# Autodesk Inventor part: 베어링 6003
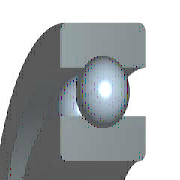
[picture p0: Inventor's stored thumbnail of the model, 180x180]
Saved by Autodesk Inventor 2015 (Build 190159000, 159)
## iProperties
Created: 2012-02
Part Number: 베어링 6003
Material: 강철, 연강
Description: 깊은 그루브 볼 베어링
Document SubType Name: Modeling
Standard: KS B 2023
Designer: mduedu
Standards Organization: KS
Language: ko-KR
Size Designation: 6003 - 17 x 35 x 10
Categories: <MemberInstance><Categories><Category DisplayName="샤프트 부품" InternalName="7f7aeb1f-a693-4053-b835-cee3144e0d98" Mnemonic="SHFT"><Category DisplayName="베어링" Inter
Density: 7.86 g/cm^3
Appearance: Steel
Mass: 39.0276 g
Surface Area: 48.7538 cm^2
Volume: 4.96535 cm^3
IsCustomPart: 1
Author: mduedu
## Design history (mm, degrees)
sketch "스케치" dims "d0" = 4.68 (= -0.26 x WD + 0.26 x BD)
  geometry: L1 (2.66, 13)-(7.34, 13); L2 (5, 13)-(5, 10.66); L3 (5, 13)-(5, 15.34); L4 (3.261, 11.434)-(0, 11.434); L5 (0, 8.5)-(10, 8.5); L6 (3.261, 14.566)-(0, 14.566); L7 (0, 17.5)-(10, 17.5); L8 (10, 8.5)-(10, 11.434); L9 (6.739, 11.434)-(10, 11.434); L10 (6.739, 14.566)-(10, 14.566); L11 (10, 17.5)-(10, 14.566); L12 (-1.4, 0)-(8.4, 0) reference; L13 (0, -0.3)-(0, 5.3) reference
  constraints: 22 end point, 4 point on line, 2 collinear, 2 perpendicular, 2 symmetric about line, 1 midpoint, 1 parallel, 14 other
  dimensions: "d9" = 17 diameter of L5 L12 (= WD); "d11" = 35 diameter of L7 L12 (= BD); "d12" = 10 distance between parallel lines of L8 L13 (= KB); "d13" = 22.868 diameter of L9 L12 (= 0.326 x BD + 0.674 x WD)
revolve "본체" stored, may be unused: angle "d6" = 90 deg
revolve "볼" stored, may be unused: angle "d7" = 90 deg
pattern_circular "IDS_ARRAYBALL[SIMPL:T]" dims angle "d3" = 360 deg
body "Solid1"
fillet "모깎기1" dims "d1" = 0.3 (= KRS)
other parameters: "WD" = 17 [user parameter; used in 5 equation terms], "BD" = 35 [user parameter; used in 5 equation terms], "KB" = 10 [user parameter; used in 1 equation term], "KRS" = 0.3 [user parameter; used in 1 equation term], "d4" = 0, "d5" = 0, "d8" = 0, "d14" = 0, "d15" = 0, "BBA" = 0 [user parameter], "BC0" = 3250000 [user parameter], "BC" = 6050000 [user parameter], "BR" = 17.5 (= 0.5 x BD) [user parameter], "WR" = 8.5 (= 0.5 x WD) [user parameter]
